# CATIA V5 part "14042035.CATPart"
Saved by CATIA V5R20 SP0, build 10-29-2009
Part number: 14042035
Definition: NONE
Nomenclature: 14042035
Source: Unknown
Description: 14042035
Bounding box of the stored display mesh (mm): x -17.5 to 70, y -35 to 24.917, z -25.1 to 25.1
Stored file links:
  C:\Users\Utente\Desktop\IO LAVORO\3D X SITO CF\X SITO\PLASTICA\RF2\14042035.CATPart
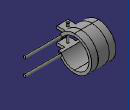
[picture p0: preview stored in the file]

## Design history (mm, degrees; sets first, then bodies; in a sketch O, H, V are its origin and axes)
Body1 "14042035" (main body)
  Solid1: solid without history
